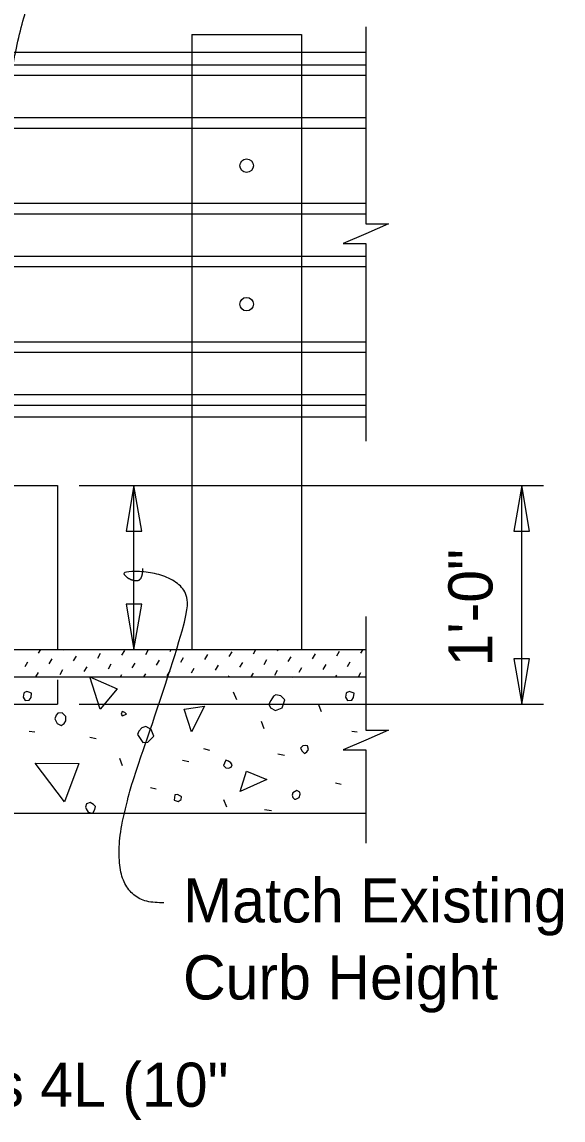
# Model space of a CAD drawing. Extents: x 21665 to 21741.5, y 56121.9 to 56164.2.
# Drawn here: x 21709.97 to 21712.44, y 56139.52 to 56144.54 of the extents above; entities that cross this region are included whole.
import ezdxf

# ---------------------------------------------------------------- set-up
doc = ezdxf.new("R2010")
doc.units = 0
for name, color, linetype in [('Dimension', 7, 'Continuous'), ('ExistSuperStruct', 7, 'Continuous'), ('Miscellaneous', 7, 'Continuous'), ('SteelMisc_h', 7, 'Continuous'), ('StrMiscConc', 7, 'Continuous'), ('StrMiscConc_h', 7, 'Continuous'), ('TextStructures', 7, 'Continuous')]:
    doc.layers.add(name, color=color, linetype=linetype)

msp = doc.modelspace()

# ---------------------------------------------------------------- linework, layer by layer
at = {"layer": 'Dimension'}
for p, q in [((21710.2339, 56142.4187), (21712.3545, 56142.4187)), ((21710.4839, 56141.6685), (21710.4839, 56142.4185)), ((21712.2545, 56142.4187), (21712.2545, 56141.4187)), ((21710.2339, 56141.4187), (21712.3545, 56141.4187))]:
    msp.add_line(p, q, dxfattribs=at)
for points in [[(21711.5431, 56144.5163), (21711.5431, 56143.6145), (21711.6465, 56143.6145), (21711.5431, 56143.5695), (21711.4398, 56143.5245), (21711.5431, 56143.5245), (21711.5431, 56142.6213)], [(21711.5431, 56141.8202), (21711.5431, 56141.3002), (21711.6465, 56141.3002), (21711.5431, 56141.2552), (21711.4398, 56141.2102), (21711.5431, 56141.2102), (21711.5431, 56140.7842)]]:
    msp.add_lwpolyline(points, dxfattribs=at)
for points in [[(21710.4839, 56142.4185), (21710.4486, 56142.2102), (21710.5191, 56142.2102)], [(21712.2546, 56142.4188), (21712.2193, 56142.2105), (21712.2899, 56142.2105)], [(21710.4839, 56141.6685), (21710.5191, 56141.8767), (21710.4486, 56141.8767)], [(21712.2546, 56141.4188), (21712.2899, 56141.627), (21712.2193, 56141.627)]]:
    msp.add_lwpolyline(points, close=True, dxfattribs=at)
for points in [[(21709.9081, 56142.4186), (21709.7047, 56145.0985), (21710.4745, 56145.0797)], [(21710.6206, 56140.5105), (21710.2765, 56140.498), (21710.7455, 56141.8308), (21710.7096, 56141.9683), (21710.5661, 56142.0261), (21710.4187, 56142.0261), (21710.4685, 56141.9843), (21710.5243, 56141.9843), (21710.5243, 56142.0401)]]:
    msp.add_open_spline(points, degree=2, dxfattribs=at)
at = {"layer": 'ExistSuperStruct'}
for p, q in [((21699.1314, 56141.6687), (21711.5431, 56141.6687)), ((21699.1314, 56141.5437), (21711.5431, 56141.5437)), ((21711.5431, 56140.9187), (21704.3514, 56140.9187))]:
    msp.add_line(p, q, dxfattribs=at)
at = {"layer": 'Miscellaneous'}
for p, q in [((21710.7484, 56144.481), (21710.7484, 56141.6687)), ((21710.7484, 56144.481), (21711.2484, 56144.481)), ((21711.2484, 56144.481), (21711.2484, 56141.6687)), ((21705.8005, 56144.3422), (21711.5431, 56144.3422)), ((21705.8005, 56144.2939), (21711.5431, 56144.2939)), ((21705.8005, 56144.1011), (21711.5431, 56144.1011)), ((21705.8005, 56144.0529), (21711.5431, 56144.0529)), ((21705.8005, 56143.7089), (21711.5431, 56143.7089)), ((21705.8005, 56143.6607), (21711.5431, 56143.6607)), ((21705.8005, 56143.4679), (21711.5431, 56143.4679)), ((21705.8005, 56143.4198), (21711.5431, 56143.4198)), ((21705.8005, 56143.0758), (21711.5431, 56143.0758)), ((21705.8005, 56143.0276), (21711.5431, 56143.0276)), ((21705.8005, 56142.8348), (21711.5431, 56142.8348)), ((21705.8005, 56142.7865), (21711.5431, 56142.7865)), ((21710.0483, 56141.6526), (21710.0577, 56141.6687)), ((21710.159, 56141.6656), (21710.1608, 56141.6687)), ((21710.3184, 56141.6297), (21710.3314, 56141.6521)), ((21710.4291, 56141.6427), (21710.442, 56141.6651)), ((21710.538, 56141.6466), (21710.5508, 56141.6687)), ((21710.6486, 56141.6595), (21710.6539, 56141.6687)), ((21710.9187, 56141.6366), (21710.9317, 56141.659)), ((21711.0293, 56141.6496), (21711.0404, 56141.6687)), ((21711.14, 56141.6626), (21711.1435, 56141.6687)), ((21711.4101, 56141.6397), (21711.423, 56141.662)), ((21711.5207, 56141.6526), (21711.53, 56141.6687)), ((21709.9865, 56141.5908), (21709.9995, 56141.6132)), ((21710.0972, 56141.6038), (21710.1101, 56141.6262)), ((21710.2078, 56141.6167), (21710.2208, 56141.6391)), ((21710.3673, 56141.5809), (21710.3802, 56141.6033)), ((21710.4762, 56141.5848), (21710.4891, 56141.6072)), ((21710.5868, 56141.5977), (21710.5998, 56141.6201)), ((21710.6974, 56141.6107), (21710.7104, 56141.6331)), ((21710.8081, 56141.6237), (21710.821, 56141.6461)), ((21710.9675, 56141.5878), (21710.9805, 56141.6102)), ((21711.0782, 56141.6008), (21711.0911, 56141.6232)), ((21711.1888, 56141.6137), (21711.2018, 56141.6361)), ((21711.2994, 56141.6267), (21711.3124, 56141.6491)), ((21711.4589, 56141.5908), (21711.4719, 56141.6132)), ((21710.0363, 56141.5437), (21710.0483, 56141.5644)), ((21710.146, 56141.5549), (21710.159, 56141.5773)), ((21710.2566, 56141.5679), (21710.2696, 56141.5903)), ((21710.4228, 56141.5437), (21710.4291, 56141.5544)), ((21710.5295, 56141.5437), (21710.538, 56141.5583)), ((21710.6356, 56141.5489), (21710.6486, 56141.5713)), ((21710.7463, 56141.5619), (21710.7592, 56141.5843)), ((21710.8569, 56141.5748), (21710.8699, 56141.5972)), ((21711.0191, 56141.5437), (21711.0293, 56141.5614)), ((21711.127, 56141.5519), (21711.14, 56141.5743)), ((21711.2376, 56141.5649), (21711.2506, 56141.5873)), ((21711.3483, 56141.5779), (21711.3612, 56141.6002)), ((21711.4056, 56141.5437), (21711.4101, 56141.5514)), ((21711.5087, 56141.5437), (21711.5207, 56141.5644)), ((21710.916, 56141.5437), (21710.9187, 56141.5484)), ((21711.2095, 56141.5402), (21711.2081, 56141.5437)), ((21710.9532, 56141.4394), (21710.9391, 56141.4748)), ((21711.3403, 56141.3847), (21711.3261, 56141.42)), ((21711.0787, 56141.3068), (21711.0663, 56141.3404)), ((21710.0058, 56141.2963), (21710.0305, 56141.2928)), ((21710.2816, 56141.268), (21710.3116, 56141.2627)), ((21711.4782, 56141.2963), (21711.5029, 56141.2928)), ((21710.8012, 56141.2167), (21710.8295, 56141.2096)), ((21710.4318, 56141.1372), (21710.4194, 56141.1708)), ((21710.7058, 56141.1637), (21710.7341, 56141.1566)), ((21711.1405, 56141.192), (21711.1706, 56141.1867)), ((21711.4039, 56141.0594), (21711.4304, 56141.0541)), ((21710.5591, 56141.0382), (21710.5856, 56141.0329)), ((21710.9072, 56140.9481), (21710.8949, 56140.9817)), ((21711.0804, 56140.9374), (21711.1122, 56140.9339))]:
    msp.add_line(p, q, dxfattribs=at)
for points in [[(21710.3293, 56141.3971), (21710.2816, 56141.5437)], [(21710.2818, 56141.5437), (21710.4071, 56141.489), (21710.3293, 56141.3971)], [(21709.9775, 56141.4519), (21709.9863, 56141.4359), (21710.0058, 56141.4377), (21710.0146, 56141.4501), (21710.0164, 56141.4695), (21710.004, 56141.4748), (21709.9952, 56141.4766), (21709.9846, 56141.4731), (21709.981, 56141.4695), (21709.9775, 56141.4519)], [(21711.107, 56141.4023), (21711.13, 56141.3899), (21711.16, 56141.4023), (21711.1724, 56141.4394), (21711.1547, 56141.4571), (21711.1318, 56141.4624), (21711.1211, 56141.4553), (21711.1088, 56141.4359), (21711.0999, 56141.42), (21711.107, 56141.4023)], [(21711.4499, 56141.4519), (21711.4587, 56141.4359), (21711.4782, 56141.4377), (21711.487, 56141.4501), (21711.4888, 56141.4695), (21711.4764, 56141.4748), (21711.4676, 56141.4766), (21711.457, 56141.4731), (21711.4534, 56141.4695), (21711.4499, 56141.4519)], [(21710.7464, 56141.2927), (21710.7128, 56141.397), (21710.8065, 56141.4094), (21710.7464, 56141.2927)], [(21710.1225, 56141.3529), (21710.1331, 56141.3316), (21710.1507, 56141.321), (21710.1649, 56141.3316), (21710.172, 56141.3423), (21710.172, 56141.3635), (21710.156, 56141.3794), (21710.1366, 56141.3776), (21710.1278, 56141.3688), (21710.1225, 56141.3529)], [(21710.43, 56141.3652), (21710.4495, 56141.3741), (21710.4424, 56141.3811), (21710.43, 56141.3864), (21710.4247, 56141.3741), (21710.43, 56141.3652)], [(21710.5007, 56141.2804), (21710.5237, 56141.2433), (21710.5467, 56141.245), (21710.5555, 56141.2539), (21710.575, 56141.2733), (21710.5626, 56141.3034), (21710.5379, 56141.3175), (21710.5202, 56141.3104), (21710.506, 56141.2963), (21710.5007, 56141.2804)], [(21711.2519, 56141.2044), (21711.2625, 56141.1938), (21711.2731, 56141.2008), (21711.2802, 56141.2114), (21711.2766, 56141.2291), (21711.2678, 56141.2309), (21711.2554, 56141.2291), (21711.2448, 56141.2185), (21711.2519, 56141.2044)], [(21710.1666, 56140.9728), (21710.0323, 56141.1496), (21710.2321, 56141.1478), (21710.1666, 56140.9728)], [(21710.9037, 56141.1283), (21710.9161, 56141.1265), (21710.9285, 56141.1318), (21710.932, 56141.1424), (21710.9267, 56141.1513), (21710.9161, 56141.1583), (21710.9037, 56141.1636), (21710.8966, 56141.1495), (21710.8931, 56141.1389), (21710.9037, 56141.1283)], [(21710.969, 56141.0205), (21710.9973, 56141.1124), (21711.091, 56141.0753), (21710.969, 56141.0205)], [(21710.6669, 56140.9799), (21710.6864, 56140.9746), (21710.6987, 56140.9834), (21710.7005, 56140.9958), (21710.697, 56140.9993), (21710.6828, 56141.0064), (21710.6704, 56141.0046), (21710.6687, 56140.9922), (21710.6669, 56140.9799)], [(21711.2165, 56140.9852), (21711.2236, 56140.9852), (21711.2377, 56140.9922), (21711.2431, 56141.0081), (21711.2413, 56141.017), (21711.2271, 56141.0241), (21711.2095, 56141.0134), (21711.2059, 56141.0028), (21711.2095, 56140.9922), (21711.2165, 56140.9852)], [(21710.2656, 56140.941), (21710.2745, 56140.9251), (21710.2957, 56140.9215), (21710.3045, 56140.9374), (21710.3081, 56140.9516), (21710.2992, 56140.9604), (21710.2833, 56140.9693), (21710.2674, 56140.964), (21710.2621, 56140.948), (21710.2656, 56140.941)]]:
    msp.add_lwpolyline(points, dxfattribs=at)
at = {"layer": 'SteelMisc_h'}
for p, q in [((21711.5431, 56144.3977), (21705.8005, 56144.3977)), ((21711.5431, 56142.731), (21705.8005, 56142.731))]:
    msp.add_line(p, q, dxfattribs=at)
for centre in [(21710.9984, 56143.8809), (21710.9984, 56143.2478)]:
    msp.add_circle(centre, 0.0312, dxfattribs=at)
at = {"layer": 'StrMiscConc'}
for p, q in [((21707.1339, 56142.4186), (21710.1339, 56142.4186)), ((21710.1339, 56142.4186), (21710.1339, 56141.6687))]:
    msp.add_line(p, q, dxfattribs=at)
at = {"layer": 'StrMiscConc_h'}
for p in [(21710.1339, 56141.531), (21707.9922, 56141.4186)]:
    msp.add_line(p, (21710.1339, 56141.4186), dxfattribs=at)

# ---------------------------------------------------------------- texts
at = {"layer": 'Dimension'}
for s, p in [('Match Existing ', (21710.7078, 56140.4214)), ('Curb Height', (21710.7078, 56140.0694)), ('Dowel Bars 4L (10" ', (21708.6024, 56139.5788))]:
    msp.add_text(s, height=0.2016, dxfattribs=at).set_placement(p)
at = {"layer": 'TextStructures'}
msp.add_text('1\'-0"', height=0.2016, rotation=90, dxfattribs=at).set_placement((21712.1213, 56141.5917))

doc.saveas('drawing.dxf')
